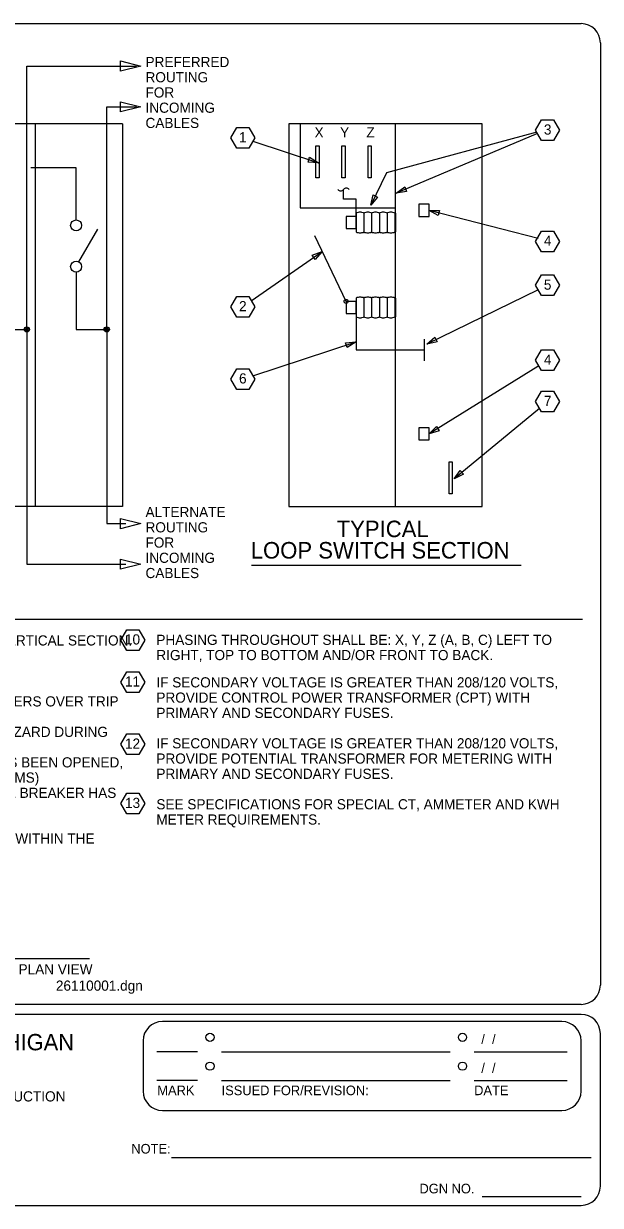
# Model space of a CAD drawing. Extents: x 10270 to 10376, y 10097 to 10174.
# Drawn here: x 10338.1 to 10375.9, y 10096.6 to 10174.1 of the extents above; entities that cross this region are included whole.
import ezdxf

# ---------------------------------------------------------------- set-up
doc = ezdxf.new("R2010")
doc.units = 0
for name, color, linetype in [('Default', 7, 'Continuous'), ('G-ANNO-LOGO', 7, 'Continuous'), ('G-ANNO-TEXT', 7, 'Continuous'), ('G-ANNO-TTLB', 7, 'Continuous'), ('G-DETL-LINE', 7, 'Continuous'), ('G-DETL-OTLN', 7, 'Continuous')]:
    doc.layers.add(name, color=color, linetype=linetype)

msp = doc.modelspace()

# ---------------------------------------------------------------- linework, layer by layer
at = {"layer": 'Default'}
msp.add_lwpolyline([(10346.028, 10133.681), (10345.636, 10133.001), (10344.852, 10133.001), (10344.46, 10133.681), (10344.852, 10134.36), (10345.636, 10134.36)], close=True, dxfattribs=at)
at = {"layer": 'G-ANNO-TEXT'}
for p, q in [((10371.797, 10166.909), (10362.532, 10163.013)), ((10353.12, 10166.413), (10357.43, 10164.998)), ((10371.838, 10160.04), (10364.68, 10161.874)), ((10353.015, 10155.937), (10357.658, 10159.181)), ((10371.842, 10156.658), (10364.544, 10153.106)), ((10353.123, 10151.023), (10359.891, 10153.243)), ((10371.814, 10151.64), (10364.68, 10147.209)), ((10371.919, 10148.884), (10366.319, 10144.26)), ((10353.033, 10138.597), (10370.72, 10138.597)), ((10271.99, 10135.053), (10374.743, 10135.053)), ((10303.885, 10112.778), (10342.41, 10112.778))]:
    msp.add_line(p, q, dxfattribs=at)
for points in [[(10373.243, 10167.138), (10372.851, 10166.459), (10372.067, 10166.459), (10371.674, 10167.138), (10372.067, 10167.817), (10372.851, 10167.817)], [(10353.244, 10166.63), (10352.852, 10165.951), (10352.067, 10165.951), (10351.675, 10166.63), (10352.067, 10167.309), (10352.852, 10167.309)], [(10356.848, 10165.365), (10357.43, 10164.998), (10356.744, 10165.048)], [(10361.305, 10162.746), (10360.866, 10162.217), (10361.005, 10162.89)], [(10363.211, 10163.118), (10362.532, 10163.013), (10363.082, 10163.425)], [(10365.284, 10161.547), (10364.68, 10161.874), (10365.367, 10161.87)], [(10373.243, 10159.842), (10372.851, 10159.163), (10372.067, 10159.163), (10371.674, 10159.842), (10372.067, 10160.521), (10372.851, 10160.521)], [(10357.016, 10158.935), (10357.658, 10159.181), (10357.207, 10158.662)], [(10373.243, 10156.959), (10372.851, 10156.279), (10372.067, 10156.279), (10371.674, 10156.959), (10372.067, 10157.638), (10372.851, 10157.638)], [(10353.244, 10155.548), (10352.852, 10154.869), (10352.067, 10154.869), (10351.675, 10155.548), (10352.067, 10156.227), (10352.852, 10156.227)], [(10365.216, 10153.248), (10364.544, 10153.106), (10365.07, 10153.548)], [(10359.205, 10153.193), (10359.891, 10153.243), (10359.309, 10152.877)], [(10373.243, 10152.041), (10372.851, 10151.361), (10372.067, 10151.361), (10371.674, 10152.041), (10372.067, 10152.72), (10372.851, 10152.72)], [(10353.244, 10150.805), (10352.852, 10150.126), (10352.067, 10150.126), (10351.675, 10150.805), (10352.067, 10151.484), (10352.852, 10151.484)], [(10373.243, 10149.329), (10372.851, 10148.65), (10372.067, 10148.65), (10371.674, 10149.329), (10372.067, 10150.009), (10372.851, 10150.009)], [(10365.334, 10147.419), (10364.68, 10147.209), (10365.158, 10147.702)], [(10366.939, 10144.556), (10366.319, 10144.26), (10366.727, 10144.813)], [(10346.028, 10130.919), (10345.636, 10130.24), (10344.852, 10130.24), (10344.46, 10130.919), (10344.852, 10131.598), (10345.636, 10131.598)], [(10346.028, 10126.843), (10345.636, 10126.164), (10344.852, 10126.164), (10344.46, 10126.843), (10344.852, 10127.522), (10345.636, 10127.522)], [(10346.028, 10122.951), (10345.636, 10122.272), (10344.852, 10122.272), (10344.46, 10122.951), (10344.852, 10123.63), (10345.636, 10123.63)]]:
    msp.add_lwpolyline(points, close=True, dxfattribs=at)
msp.add_lwpolyline([(10371.755, 10166.996), (10361.888, 10164.339), (10360.866, 10162.217)], dxfattribs=at)
at = {"layer": 'G-ANNO-TTLB'}
for p, q in [((10375.918, 10172.861), (10375.918, 10111.037)), ((10374.658, 10109.776), (10271.638, 10109.776)), ((10345.922, 10107.384), (10345.922, 10104.078)), ((10374.653, 10104.078), (10374.653, 10107.384)), ((10349.497, 10106.667), (10346.813, 10106.667)), ((10351.071, 10106.667), (10366.067, 10106.667)), ((10367.64, 10106.667), (10373.746, 10106.667)), ((10349.497, 10104.776), (10346.813, 10104.776)), ((10351.071, 10104.776), (10366.067, 10104.776)), ((10367.64, 10104.776), (10373.746, 10104.776)), ((10347.787, 10099.737), (10375.322, 10099.737)), ((10368.172, 10097.157), (10374.658, 10097.157))]:
    msp.add_line(p, q, dxfattribs=at)
for points in [[(10271.638, 10174.128), (10374.658, 10174.128)], [(10374.658, 10109.119), (10271.638, 10109.119)], [(10373.392, 10108.645), (10347.183, 10108.645)], [(10375.918, 10097.847), (10375.918, 10107.858)], [(10347.183, 10102.817), (10373.392, 10102.817)], [(10271.638, 10096.586), (10374.658, 10096.586)]]:
    msp.add_lwpolyline(points, dxfattribs=at)
for centre in [(10350.306, 10107.613), (10366.875, 10107.613), (10350.306, 10105.722), (10366.875, 10105.722)]:
    msp.add_circle(centre, 0.27, dxfattribs=at)
for centre, start, end in [((10374.658, 10172.868), 0, 90), ((10374.658, 10111.037), 270, 0), ((10347.183, 10107.384), 90, 180), ((10373.392, 10107.384), 0, 90), ((10374.658, 10107.858), 0, 90), ((10347.183, 10104.078), 180, 270), ((10373.392, 10104.078), 270, 0), ((10374.658, 10097.847), 270, 0)]:
    msp.add_arc(centre, 1.261, start, end, dxfattribs=at)
at = {"layer": 'G-DETL-LINE'}
for p, q in [((10338.296, 10154.061), (10338.296, 10171.344)), ((10338.296, 10171.344), (10345.488, 10171.344)), ((10343.537, 10154.061), (10343.537, 10168.664)), ((10343.537, 10168.664), (10345.488, 10168.664)), ((10341.528, 10161.967), (10341.528, 10164.67)), ((10341.528, 10161.247), (10341.528, 10161.967)), ((10359.9, 10161.696), (10359.9, 10160.459)), ((10360.406, 10161.696), (10360.406, 10160.459)), ((10360.912, 10161.696), (10360.912, 10160.459)), ((10361.419, 10161.696), (10361.419, 10160.459)), ((10361.925, 10161.696), (10361.925, 10160.459)), ((10362.431, 10161.696), (10362.431, 10160.459)), ((10341.709, 10158.495), (10342.943, 10160.633)), ((10359.238, 10155.902), (10357.188, 10160.215)), ((10341.528, 10157.822), (10341.528, 10157.101)), ((10341.528, 10157.101), (10341.528, 10154.061)), ((10359.9, 10156.122), (10359.9, 10154.885)), ((10360.406, 10156.122), (10360.406, 10154.885)), ((10360.912, 10156.122), (10360.912, 10154.885)), ((10361.419, 10156.122), (10361.419, 10154.885)), ((10361.925, 10156.122), (10361.925, 10154.885)), ((10362.431, 10156.122), (10362.431, 10154.885)), ((10336.287, 10154.061), (10338.296, 10154.061)), ((10338.296, 10154.061), (10338.296, 10138.654)), ((10341.528, 10154.061), (10343.537, 10154.061)), ((10343.537, 10154.061), (10343.537, 10141.333)), ((10364.349, 10153.42), (10364.349, 10152.013)), ((10343.537, 10141.333), (10344.796, 10141.333)), ((10338.296, 10138.654), (10344.796, 10138.654))]:
    msp.add_line(p, q, dxfattribs=at)
for points in [[(10344.444, 10171.677), (10345.778, 10171.344), (10344.444, 10171.01)], [(10344.444, 10168.997), (10345.778, 10168.664), (10344.444, 10168.331)], [(10357.258, 10166.106), (10357.461, 10166.106), (10357.461, 10164.005), (10357.258, 10164.005)], [(10358.968, 10166.106), (10359.172, 10166.106), (10359.172, 10164.005), (10358.968, 10164.005)], [(10360.679, 10166.106), (10360.882, 10166.106), (10360.882, 10164.005), (10360.679, 10164.005)], [(10364.68, 10162.272), (10364.018, 10162.272), (10364.018, 10161.476), (10364.68, 10161.476)], [(10359.9, 10161.476), (10359.238, 10161.476), (10359.238, 10160.679), (10359.9, 10160.679)], [(10359.9, 10155.902), (10359.238, 10155.902), (10359.238, 10155.105), (10359.9, 10155.105)], [(10364.68, 10147.607), (10364.018, 10147.607), (10364.018, 10146.811), (10364.68, 10146.811)], [(10365.992, 10145.373), (10366.195, 10145.373), (10366.195, 10143.272), (10365.992, 10143.272)], [(10344.444, 10141.652), (10345.778, 10141.319), (10344.444, 10140.985)], [(10344.444, 10138.989), (10345.778, 10138.655), (10344.444, 10138.322)]]:
    msp.add_lwpolyline(points, close=True, dxfattribs=at)
for points in [[(10341.528, 10164.67), (10338.546, 10164.67)], [(10359.9, 10161.476), (10359.9, 10162.615), (10359.07, 10162.615), (10359.07, 10163.242)], [(10362.431, 10161.696), (10362.48, 10161.696), (10362.48, 10160.459), (10362.431, 10160.459)], [(10362.431, 10156.122), (10362.48, 10156.122), (10362.48, 10154.885), (10362.431, 10154.885)], [(10359.9, 10155.105), (10359.9, 10152.716), (10364.349, 10152.716)]]:
    msp.add_lwpolyline(points, dxfattribs=at)
for centre, radius in [((10341.528, 10160.886), 0.36), ((10341.528, 10158.182), 0.36), ((10359.238, 10155.902), 0.131), ((10338.296, 10154.061), 0.174), ((10338.296, 10154.061), 0.0977), ((10343.537, 10154.061), 0.174), ((10343.537, 10154.061), 0.0977), ((10338.296, 10154.061), 0.0326), ((10343.537, 10154.061), 0.0326)]:
    msp.add_circle(centre, radius, dxfattribs=at)
for centre, start, end in [((10358.887, 10163.38), 216.8699, 323.1301), ((10359.253, 10163.105), 36.8699, 143.1301)]:
    msp.add_arc(centre, 0.229, start, end, dxfattribs=at)
for centre, start_param, end_param in [((10360.153, 10161.696), 0, 3.141598), ((10360.659, 10161.696), 0, 3.141598), ((10361.165, 10161.696), 0, 3.141598), ((10361.672, 10161.696), 0, 3.141598), ((10362.178, 10161.696), 0, 3.141598), ((10360.153, 10160.459), 3.141587, 6.283185), ((10360.659, 10160.459), 3.141587, 6.283185), ((10361.165, 10160.459), 3.141587, 6.283185), ((10361.672, 10160.459), 3.141587, 6.283185), ((10362.178, 10160.459), 3.141587, 6.283185), ((10360.153, 10156.122), 0, 3.141598), ((10360.659, 10156.122), 0, 3.141598), ((10361.165, 10156.122), 0, 3.141598), ((10361.672, 10156.122), 0, 3.141598), ((10362.178, 10156.122), 0, 3.141598), ((10360.153, 10154.885), 3.141587, 6.283185), ((10360.659, 10154.885), 3.141587, 6.283185), ((10361.165, 10154.885), 3.141587, 6.283185), ((10361.672, 10154.885), 3.141587, 6.283185), ((10362.178, 10154.885), 3.141587, 6.283185)]:
    msp.add_ellipse(centre, major_axis=(0.253, 0), ratio=0.209138, start_param=start_param, end_param=end_param, dxfattribs=at)
at = {"layer": 'G-DETL-OTLN'}
for p, q in [((10344.565, 10167.562), (10278.273, 10167.562)), ((10338.844, 10167.562), (10338.844, 10142.435)), ((10344.565, 10167.562), (10344.565, 10142.435)), ((10362.48, 10142.435), (10362.48, 10167.562)), ((10344.565, 10142.435), (10278.273, 10142.435))]:
    msp.add_line(p, q, dxfattribs=at)
msp.add_lwpolyline([(10355.481, 10142.435), (10368.169, 10142.435), (10368.169, 10167.562), (10355.481, 10167.562)], close=True, dxfattribs=at)
msp.add_lwpolyline([(10356.234, 10167.562), (10356.234, 10162.045), (10362.48, 10162.045)], dxfattribs=at)

# ---------------------------------------------------------------- texts
at = {"layer": 'Default'}
msp.add_text('10', height=0.6667, dxfattribs=at).set_placement((10344.73, 10133.39))
at = {"layer": 'G-ANNO-LOGO'}
for s, height, p in [('ICHIGAN', 1.0717, (10335.417, 10106.761)), ('ONSTRUCTION', 0.66978, (10334.264, 10103.402))]:
    msp.add_text(s, height=height, dxfattribs=at).set_placement(p)
at = {"layer": 'G-ANNO-TEXT'}
for s, height, p in [('PREFERRED', 0.6667, (10346.079, 10171.279)), ('ROUTING', 0.6667, (10346.079, 10170.279)), ('FOR', 0.6667, (10346.079, 10169.279)), ('INCOMING', 0.6667, (10346.079, 10168.279)), ('CABLES', 0.6667, (10346.079, 10167.279)), ('3', 0.667, (10372.214, 10166.848)), ('1', 0.667, (10352.215, 10166.34)), ('X', 0.667, (10357.169, 10166.657)), ('Y', 0.667, (10358.842, 10166.657)), ('Z', 0.667, (10360.564, 10166.657)), ('4', 0.667, (10372.214, 10159.551)), ('5', 0.667, (10372.214, 10156.668)), ('2', 0.667, (10352.215, 10155.258)), ('4', 0.667, (10372.214, 10151.75)), ('6', 0.667, (10352.215, 10150.515)), ('7', 0.667, (10372.214, 10149.039)), ('ALTERNATE', 0.6667, (10346.079, 10141.745)), ('ROUTING', 0.6667, (10346.079, 10140.745)), ('TYPICAL', 1.0833, (10358.62, 10140.432)), ('FOR', 0.6667, (10346.079, 10139.745)), ('LOOP SWITCH SECTION', 1.08333, (10352.982, 10139.03)), ('INCOMING', 0.6667, (10346.079, 10138.745)), ('CABLES', 0.6667, (10346.079, 10137.745)), ('THE FIRE PUMP DISCONNECTING MEANS SHALL BE IN A DEDICATED FULLY-BARRIERED VERTICAL SECTION.', 0.66667, (10297.699, 10133.323)), ('PHASING THROUGHOUT SHALL BE: X, Y, Z (A, B, C) LEFT TO', 0.66667, (10346.791, 10133.362)), ('RIGHT, TOP TO BOTTOM AND/OR FRONT TO BACK.', 0.66667, (10346.791, 10132.362)), ('11', 0.6667, (10344.73, 10130.629)), ('IF SECONDARY VOLTAGE IS GREATER THAN 208/120 VOLTS,', 0.66667, (10346.791, 10130.572)), ('PROVIDE CONTROL POWER TRANSFORMER (CPT) WITH', 0.66667, (10346.791, 10129.572)), ('   * CONCEAL CIRCUIT BREAKER TRIP BUTTONS BEHIND CUBICLE DOOR, OR PROVIDE COVERS OVER TRIP', 0.66667, (10297.699, 10129.323)), ('PRIMARY AND SECONDARY FUSES. ', 0.66667, (10346.791, 10128.572)), ('   * EQUIP WITH A REDUCED ENERGY LET-THROUGH FEATURE, TO REDUCE ARC FLASH HAZARD DURING', 0.66667, (10297.699, 10127.323)), ('12', 0.6667, (10344.73, 10126.553)), ('IF SECONDARY VOLTAGE IS GREATER THAN 208/120 VOLTS,', 0.66667, (10346.791, 10126.572)), ('PROVIDE POTENTIAL TRANSFORMER FOR METERING WITH', 0.66667, (10346.791, 10125.572)), ('   * EQUIP WITH AN AUXILIARY DRY CONTACT TO CHANGE STATE WHEN THE BREAKER HAS BEEN OPENED,', 0.66667, (10297.699, 10125.323)), ('      FOR REMOTE SUPERVISORY MONITORING BY THE BUILDING MANAGEMENT SYSTEM (BMS)', 0.66667, (10297.699, 10124.323)), ('PRIMARY AND SECONDARY FUSES. ', 0.66667, (10346.791, 10124.572)), ('   * THE CELL POSITION SHALL BE MONITORED BY THE BMS, TO CHANGE STATE WHEN THE BREAKER HAS', 0.66667, (10297.699, 10123.323)), ('13', 0.6667, (10344.735, 10122.661)), ('SEE SPECIFICATIONS FOR SPECIAL CT, AMMETER AND KWH', 0.66667, (10346.791, 10122.572)), ('METER REQUIREMENTS.', 0.66667, (10346.791, 10121.572)), ('THE KEY FOR THE FIRE PUMP CIRCUIT BREAKER LOCK SHALL BE STORED IN A KEY BOX WITHIN THE', 0.66667, (10298.551, 10120.323)), ('NO SCALE    -    REVERSE END-TO-END WHEN APPROPRIATE TO MATCH PLAN VIEW', 0.66667, (10306.148, 10111.743)), ('26110001.dgn', 0.66667, (10340.199, 10110.671))]:
    msp.add_text(s, height=height, dxfattribs=at).set_placement(p)
at = {"layer": 'G-ANNO-TTLB'}
for s, height, p in [('  /  /  ', 0.6304, (10367.64, 10107.177)), ('  /  /  ', 0.6304, (10367.64, 10105.286)), ('MARK', 0.6304, (10346.853, 10103.815)), ('ISSUED FOR/REVISION:', 0.63039, (10351.071, 10103.815)), ('DATE', 0.6304, (10367.64, 10103.815)), ('NOTE:', 0.6304, (10345.149, 10099.986)), ('DGN NO.', 0.6304, (10364.052, 10097.373))]:
    msp.add_text(s, height=height, dxfattribs=at).set_placement(p)

doc.saveas('drawing.dxf')
